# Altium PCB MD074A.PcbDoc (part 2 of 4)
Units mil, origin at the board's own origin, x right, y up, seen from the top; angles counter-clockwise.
Board outline 3224.41 x 4078.74 mil, 4 copper layers (Top Layer, Signal Layer 1, Signal Layer 2, Bottom Layer), stack 61.2 mil thick; 217 components, 121 nets, 624 pads, 901 vias.
Unrouted connection lines stored in the file: 116.
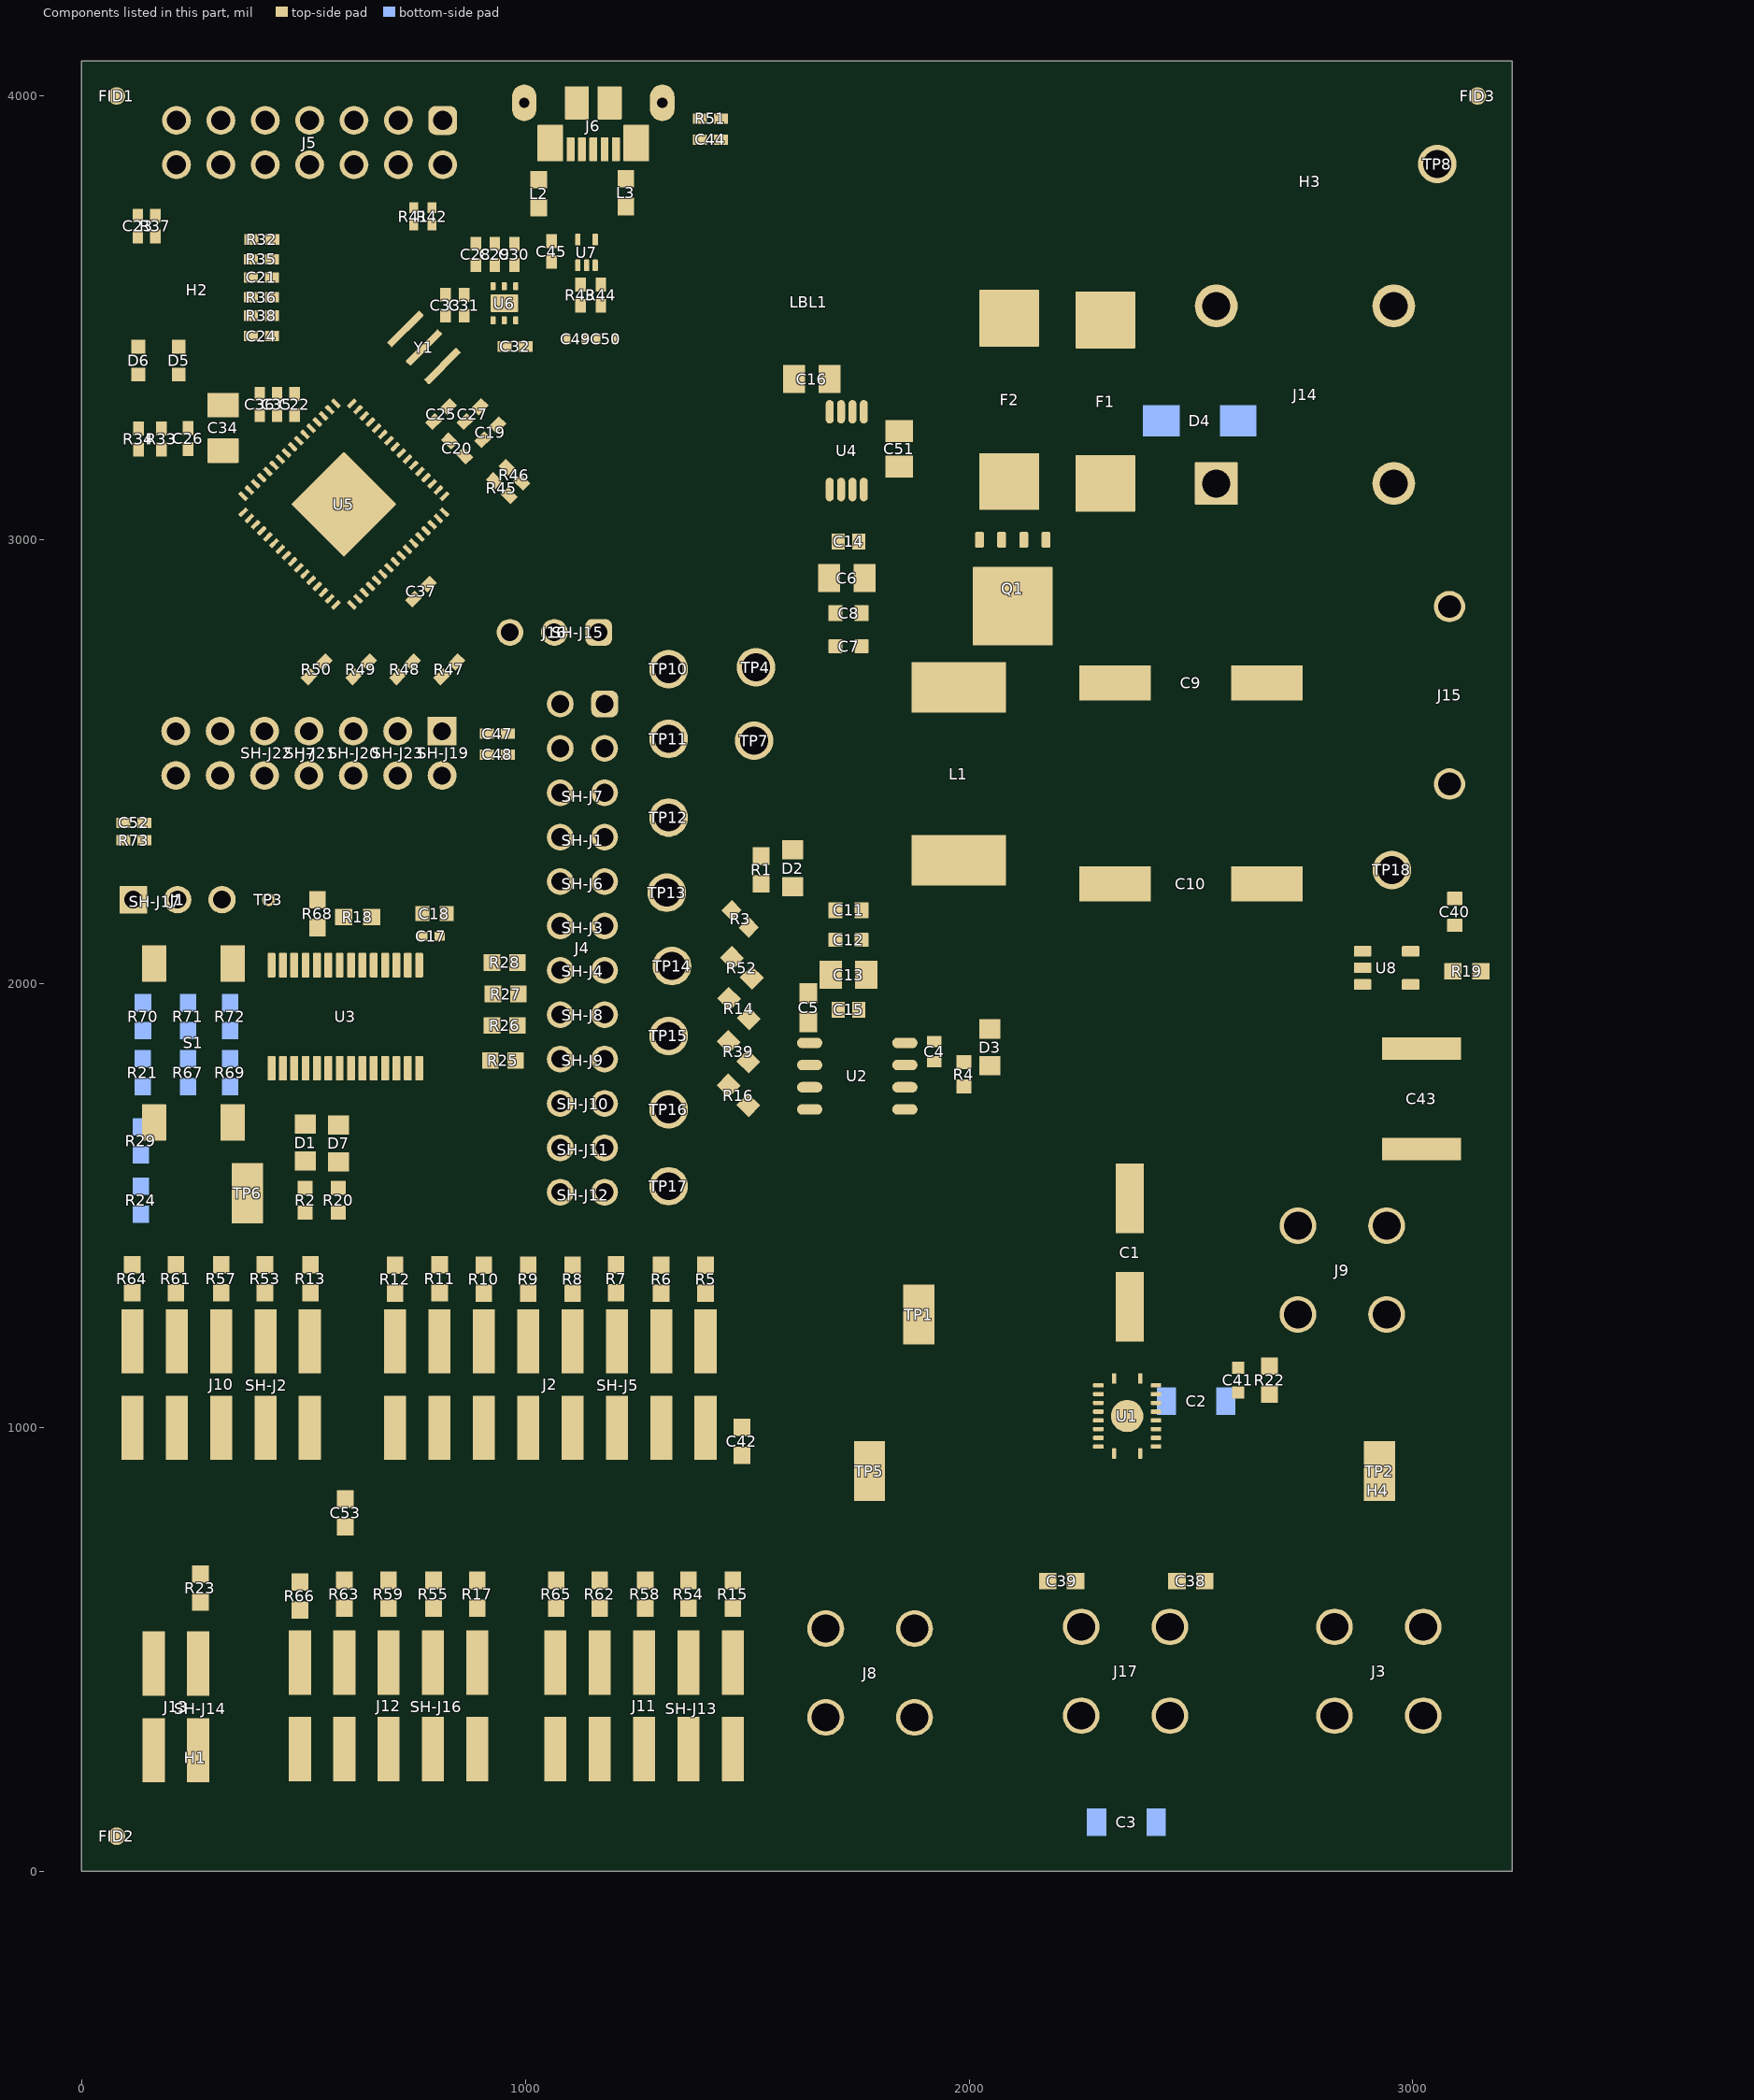
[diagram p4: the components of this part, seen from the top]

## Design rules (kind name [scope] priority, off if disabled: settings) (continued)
PolygonConnect PolygonConnect_17 [All vs IsNamedPolygon('TOP_LAYER_OUT1_P103')] p76: connectstyle=Direct reliefconductorwidth=10 reliefentries=4 polygonreliefangle="90 Angle" airgapwidth=10
PolygonConnect PolygonConnect_16 [All vs IsNamedPolygon('TOP_LAYER_OUT1_P000')] p77: connectstyle=Direct reliefconductorwidth=10 reliefentries=4 polygonreliefangle="90 Angle" airgapwidth=10
PolygonConnect PolygonConnect_15 [All vs IsNamedPolygon('TOP_LAYER_NONET_P093')] p78: connectstyle=Direct reliefconductorwidth=10 reliefentries=4 polygonreliefangle="90 Angle" airgapwidth=10
PolygonConnect PolygonConnect_14 [All vs IsNamedPolygon('TOP_LAYER_OUT2_P099')] p79: connectstyle=Direct reliefconductorwidth=10 reliefentries=4 polygonreliefangle="90 Angle" airgapwidth=10
PolygonConnect PolygonConnect_13 [All vs IsNamedPolygon('TOP_LAYER_OUT1_P000')] p80: connectstyle=Direct reliefconductorwidth=10 reliefentries=4 polygonreliefangle="90 Angle" airgapwidth=10
PolygonConnect PolygonConnect_12 [All vs IsNamedPolygon('BOTTOM_LAYER_NONET_P079') Or  IsNamedPolygon('SIGNAL_LAYER_2_NONET_P078') Or  IsNamedPolygon('SIGNAL_LAYER_1_NONET_P077') Or  IsNamedPolygon('TOP_LAYER_NONET_P083') Or  IsNamedPolygon('BOTTOM_LAYER_NONET_P072') Or  IsNamedPolygon('SIGNAL_LAYER_2_NONET_P070') Or  IsNamedPolygon('SIGNAL_LAYER_1_NONET_P059') Or  IsNamedPolygon('TOP_LAYER_OUT2_P058') Or  IsNamedPolygon('BOTTOM_LAYER_NONET_P056') Or  IsNamedPolygon('SIGNAL_LAYER_2_NONET_P054') Or  IsNamedPolygon('SIGNAL_LAYER_1_NONET_P052') Or  IsNamedPolygon('TOP_LAYER_OUT1_P050') Or  IsNamedPolygon('BOTTOM_LAYER_VM_P044') Or  IsNamedPolygon('SIGNAL_LAYER_2_VM_P042') Or  IsNamedPolygon('SIGNAL_LAYER_1_VM_P040') Or  IsNamedPolygon('TOP_LAYER_VM_P038') Or  IsNamedPolygon('BOTTOM_LAYER_VM_P036') Or  IsNamedPolygon('SIGNAL_LAYER_2_VM_P018') Or  IsNamedPolygon('SIGNAL_LAYER_1_VM_P016') Or  IsNamedPolygon('TOP_LAYER_VM_P002')] p81: connectstyle=Direct reliefconductorwidth=10 reliefentries=4 polygonreliefangle="90 Angle" airgapwidth=10
PolygonConnect PolygonConnect_11 [All vs IsNamedPolygon('TOP_LAYER_NONET_P089') Or  IsNamedPolygon('TOP_LAYER_NONET_P090')] p82: connectstyle=Direct reliefconductorwidth=10 reliefentries=4 polygonreliefangle="90 Angle" airgapwidth=10
PolygonConnect PolygonConnect_10 [All vs IsNamedPolygon('BOTTOM_LAYER_EZFET_USB_SHIELD_P002') Or  IsNamedPolygon('TOP_LAYER_EZFET_USB_SHIELD_P173') Or  IsNamedPolygon('SIGNAL_LAYER_2_EZFET_VBUS_P018') Or  IsNamedPolygon('SIGNAL_LAYER_2_EZFET_VCC_P016')] p83: connectstyle=Direct reliefconductorwidth=10 reliefentries=4 polygonreliefangle="90 Angle" airgapwidth=10
PolygonConnect PolygonConnect_9 [All vs IsNamedPolygon('TOP_LAYER_VM_P123') Or  IsNamedPolygon('TOP_LAYER_VM_P123') Or  IsNamedPolygon('TOP_LAYER_VM_P123')] p84: connectstyle=Direct reliefconductorwidth=10 reliefentries=4 polygonreliefangle="90 Angle" airgapwidth=10
PolygonConnect PolygonConnect_8 [All vs IsNamedPolygon('TOP_LAYER_NONET_P072')] p85: connectstyle=Direct reliefconductorwidth=10 reliefentries=4 polygonreliefangle="90 Angle" airgapwidth=10
PolygonConnect PolygonConnect_7 [All vs IsNamedPolygon('TOP_LAYER_NONET_P072')] p86: connectstyle=Direct reliefconductorwidth=10 reliefentries=4 polygonreliefangle="90 Angle" airgapwidth=10
PolygonConnect PolygonConnect_6 [All vs IsNamedPolygon('TOP_LAYER_VM_P042')] p87: connectstyle=Direct reliefconductorwidth=10 reliefentries=4 polygonreliefangle="90 Angle" airgapwidth=10
PolygonConnect PolygonConnect_5 [All vs IsNamedPolygon('TOP_LAYER_VM_P044')] p88: connectstyle=Direct reliefconductorwidth=10 reliefentries=4 polygonreliefangle="90 Angle" airgapwidth=10
PolygonConnect PolygonConnect_4 [All vs IsNamedPolygon('TOP_LAYER_VM_P046')] p89: connectstyle=Direct reliefconductorwidth=10 reliefentries=4 polygonreliefangle="90 Angle" airgapwidth=10
PolygonConnect PolygonConnect_3 [All vs IsNamedPolygon('TOP_LAYER_GND_P036') Or  IsNamedPolygon('TOP_LAYER_OUT2_P040') Or  IsNamedPolygon('TOP_LAYER_OUT1_P038')] p90: connectstyle=Direct reliefconductorwidth=10 reliefentries=4 polygonreliefangle="90 Angle" airgapwidth=10
PolygonConnect PolygonConnect_2 [InNet('EZFET_VBUS') vs IsNamedPolygon('TOP_LAYER_EZFET_VBUS_P008')] p91: connectstyle=Direct reliefconductorwidth=10 reliefentries=4 polygonreliefangle="90 Angle" airgapwidth=10
PolygonConnect PolygonConnect_1 [InNetClass('Power-Net') vs IsNamedPolygon('TOP_LAYER_EZFET_USB_SHIELD_P173')] p92: connectstyle=Direct reliefconductorwidth=10 reliefentries=4 polygonreliefangle="90 Angle" airgapwidth=10
RoutingVias ThermalPadVias [IsVia and InAnyComponent] p1: holewidth=7.87 width=19.68 viastyle="Through Hole" minholewidth=7.87 minwidth=19.68 maxholewidth=12.99 maxwidth=23.62
RoutingVias [All] p2: holewidth=16 width=34 viastyle="Through Hole" minholewidth=7.87 minwidth=26 maxholewidth=40 maxwidth=65
SilkToBoardRegionClearance [Not ((IsComment or IsDesignator) And (Hide <> 'False')) and not InRegion(1000,500,4000,800)] p1:
SilkToSilkClearance SilkToSilkClearance_Pb-FreeLogo [(HasFootprint('Pb-Free_Overlay_Medium') OR HasFootprint('Pb-Free_Overlay_Small')) vs (HasFootprint('Pb-Free_Overlay_Medium') OR HasFootprint('Pb-Free_Overlay_Small'))] p1: silktosilkclearance=0
SilkToSilkClearance [All] p2: silktosilkclearance=3.94
SilkToSolderMaskClearance SilkToComponentPadClearance [(IsPad or IsFill or IsRegion) and InAnycomponent] p1: minsilkscreentomaskgap=5 clearancetoexposedcopper=TRUE
SilkToSolderMaskClearance "Silk to Solder Mask Opening" [All] p2: minsilkscreentomaskgap=3.94 clearancetoexposedcopper=FALSE
SolderMaskExpansion [All] p1: expansion=1.97 istentingtop=FALSE
UnRoutedNet [All] p1: checkbadconnections=TRUE
Width [All] p1: maxlimit=100 minlimit=6 preferedwidth=10 checkconnectedcopper=TRUE
13 further rules are at their usual default settings.

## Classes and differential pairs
component class MD074A_Hardware: !PCB1 FID1 FID2 FID3 H1 H2 H3 H4 LBL1 Logo1 Logo2 Logo3 Logo4 Logo5 LOGO6 ZZ1 ZZ2 ZZ3 ZZ4
component class MD074A: C1 C2 C3 C4 C5 C6 C7 C8 C9 C10 C11 C12 C13 C14 C15 C16 C17 C18 C38 C39 C40 C41 C42 C43 C51 C52 C53 D1 D2 D3 D4 D7 F1 F2 J1 J2 J3 J4 J8 J9 J10 J11 J12 J13 J14 J15 J16 J17 L1 Q1 R1 R2 R3 R4 R5 R6 R7 R8 R9 R10 R11 R12 R13 R14 R15 R16 R17 R18 R19 R20 R21 R22 R23 R24 R25 R26 R27 R28 R29 R39 R52 R53 R54 R55 R57 R58 R59 R61 R62 R63 R64 R65 R66 R67 R68 R69 R70 R71 R72 R73 S1 SH-J1 SH-J2 SH-J3 SH-J4 SH-J5 SH-J6 SH-J7 SH-J8 SH-J9 SH-J10 SH-J11 SH-J12 SH-J13 SH-J14 SH-J15 SH-J16 SH-J17 TP1 TP2 TP3 TP4 TP5 TP6 TP7 TP8 TP10 TP11 TP12 TP13 TP14 TP15 TP16 TP17 TP18 U1 U2 U3 U4 U8
component class Shunt: SH-J1 SH-J2 SH-J3 SH-J4 SH-J5 SH-J6 SH-J7 SH-J8 SH-J9 SH-J10 SH-J11 SH-J12 SH-J13 SH-J14 SH-J15 SH-J16 SH-J17 SH-J19 SH-J20 SH-J21 SH-J22 SH-J23
net class Power-Net: 3V3_MCU EZFET_VBUS EZFET_VCC GND
component class Header: J2 J5 J7 J10 J11 J12 J13 J16
component class ezFET: C19 C20 C21 C22 C23 C24 C25 C26 C27 C28 C29 C30 C31 C32 C33 C34 C35 C36 C37 C44 C45 C47 C48 C49 C50 D5 D6 J5 J6 J7 L2 L3 R32 R33 R34 R35 R36 R37 R38 R41 R42 R43 R44 R45 R46 R47 R48 R49 R50 R51 SH-J19 SH-J20 SH-J21 SH-J22 SH-J23 U5 U6 U7 Y1
component class Logo: Logo2
component class FiducialMark: FID1 FID2 FID3
component class AssemblyNote: ZZ1 ZZ2 ZZ3 ZZ4
component class Label: LBL1
differential pair USB_D: +USB_D_P -USB_D_N
differential pair EZFET_D: +EZFET_D_P -EZFET_D_N

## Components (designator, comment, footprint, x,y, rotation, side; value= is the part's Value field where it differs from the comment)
C1 "EEE-2AA100UP" SM_RADIAL_E 2362.2,1393.7 r270 top value=10uF
C2 "C3216X7R2A104K160AA" 1206_180 2511.81,1059.06 r180 bottom value=0.1uF
C3 "C3216X7R2A104K160AA" 1206_180 2354.33,110.24 r0 bottom value=0.1uF
C4 "CL10B104JB8NNNC" FP-CL10-0_1-MFG 1921.26,1846.46 r270 top value=0.1uF
C5 "CL10A226MQ8NUNE" FP-CL10-IPC_A 1637.8,1945.94 r90 top value=22uF
C6 "885012207103" 0805_HV 1724.41,2913.39 r0 top value=1uF
C7 "885012206095" FP-885012206095_0603-MFG 1728.35,2759.84 r0 top value=100nF
C8 "CC0603KPX7R9BB103" FP-CC0603-DA-MFG 1728.35,2834.65 r0 top value="10 nF"
C9 "EEE-FK1H151P" SM_RADIAL_G 2500,2677.17 r0 top value=150uF
C10 "EEE-FK1H151P" SM_RADIAL_G 2500,2224.41 r0 top value=150uF
C11 "CC0603KPX7R9BB103" FP-CC0603-DA-MFG 1728.35,2165.35 r0 top value="10 nF"
C12 "885012206095" FP-885012206095_0603-MFG 1728.35,2098.43 r0 top value=100nF
C13 "885012207103" 0805_HV 1728.35,2019.68 r0 top value=1uF
C14 "1nF" FP-C0603C-CF-MFG#1 1732.28,2996.06 r180 top value="1,000 pF"
C15 "1nF" FP-C0603C-CF-MFG#2 1728.35,1940.94 r180 top value="1,000 pF"
C16 "885012007057" 0805_HV 1645.67,3362.2 r180 top value=100pF
C17 "Capacitor" 0402_065L 787.4,2106.3 r0 top value=4.7uF
C18 "885012206020" 0603L 795.28,2157.48 r0 top value=0.1uF
C19 "C1005X5R1A475M050BC" 0402 921.15,3242.01 r45 top value=4.7uF
C20 "GRM155R61A104KA01D" 0402 846.51,3205.86 r315 top value=0.1uF
C21 "C1005C0G1H330J050BA" 0402 405.6,3590.85 r180 top value=33pF
C22 "GRM155R61A104KA01D" 0402 480.31,3305.13 r90 top value=0.1uF
C23 "GRM155R71H102KA01D" 0402 127.1,3706.64 r270 top value=1000pF
C24 "C1005C0G1H330J050BA" 0402 405.6,3458.9 r180 top value=33pF
C25 "GRM155R61A224KE19D" 0402 810.36,3283.06 r45 top value=0.22uF
C26 "GRM155R61C474KE01" 0402 240.16,3228.35 r90 top value=0.47uF
C27 "GRM155R61A224KE19D" 0402 881.2,3283.06 r45 top value=0.22uF
C28 "885012105012" 0402 888.87,3642.71 r90 top value=1uF
C29 "GRM155R61A104KA01D" 0402 931.31,3642.73 r90 top value=0.1uF
C30 "GRM155R71C103KA01D" 0402 975.35,3642.71 r90 top value=0.01uF
C31 "2.2uF" 0402 862.4,3528.56 r90 top
C32 "GRM155R71C103KA01D" 0402 976.95,3435.27 r0 top value=0.01uF
C33 "885012105012" 0402 820.1,3528.56 r90 top value=1uF
C34 "T520A106M010ATE080" 3216-18 318.9,3251.97 r90 top value=10uF
C35 "GRM155R61A104KA01D" 0402 440.55,3305.13 r90 top value=0.1uF
C36 "GRM155R61A104KA01D" 0402 401.77,3305.13 r90 top value=0.1uF
C37 "GRM155R61A104KA01D" 0402 764.94,2883.18 r225 top value=0.1uF
C38 "CGA3E2X7R2A102K080AA" 0603 2500,653.54 r0 top value=1000pF
C39 "CGA3E2X7R2A102K080AA" 0603 2208.66,653.54 r180 top value=1000pF
C40 "GRM188R61E475KE15D" FP-GRM188R61E475KE15D_0603-MFG 3094.49,2161.42 r270 top value=4.7µF
C41 "CGA3E2X7R1E104K080AA" FP-CGA3E-0_3-0_1-MFG 2606.3,1106.3 r90 top
C42 "CGA3E2X7R2A102K080AA" 0603 1488.19,968.5 r90 top value=1000pF
C43 "C5750X7S2A106M230KE" FP-C5750-230-0_5-MFG 3019.68,1740.16 r90 top
C44 "GRM155R61A224KE19D" 0402 1417.32,3901.57 r0 top value=0.22uF
C45 "GRM155R61A104KA01D" 0402 1059.06,3649.61 r90 top value=0.1uF
C47 "GRM1555C1H100FA01D" 0402 937.01,2562.99 r180 top value=10pF
C48 "GRM1555C1H100FA01D" 0402 937.01,2515.75 r180 top value=10pF
C49 "GRM1555C1H100FA01D" 0402S 1113.86,3452.76 r180 top value=10pF
C50 "GRM1555C1H100FA01D" 0402S 1181.42,3452.76 r0 top value=10pF
C51 "C2012X5R1H225K125AB" 0805_HV 1842.52,3204.72 r90 top value=2.2uF
C52 "GRM155R71H102KA01D" 0402 118.11,2362.2 r0 top value=1000pF
C53 "CGA3E2X7R1H104K080AA" 0603 594.49,807.09 r270 top value=0.1uF
D1 "150080VS75000" 0805_A 503.94,1641.73 r90 top
D2 "150080SS75000" 0805_A 1602.36,2259.84 r90 top
D3 "150080VS75000" 0805_A 2047.24,1856.3 r90 top
D4 "SMAJ36CA" FP-SMAJ-CA-MFG 2519.68,3267.72 r180 bottom
D5 "150060RS75000" WL-SMCW_RED 218.95,3403.78 r270 top value=Red
D6 "CMP-0002894-2" WL-SMCW_GREEN 128.28,3403.78 r270 top value=Green
D7 "150080VS75000" 0805_A 578.74,1639.76 r90 top
F1 "0463015.ER" Fuse_0463 2307.09,3311.02 r90 top
F2 "0463030.ER" Fuse_0463 2090.55,3314.96 r90 top
FID1 "Fiducial" Fiducial10-20 78.74,4000 r0 top
FID2 "Fiducial" Fiducial10-20 78.74,78.74 r90 top
FID3 "Fiducial" Fiducial10-20 3145.67,4000 r0 top
H1 "SJ-5303 (CLEAR)" Bumpon_SJ5003Transparent 255.91,255.91 r0 bottom
H2 "SJ-5303 (CLEAR)" Bumpon_SJ5003Transparent 259.84,3562.99 r0 bottom
H3 "SJ-5303 (CLEAR)" Bumpon_SJ5003Transparent 2767.72,3807.09 r0 bottom
H4 "SJ-5303 (CLEAR)" Bumpon_SJ5003Transparent 2921.26,858.27 r180 bottom
J1 "PR20203VBNN" FP-PR20203VBNN-MFG 216.54,2188.98 r0 top
J2 "TSM-108-01-L-DV" Samtec_TSM-108-01-x-DV 1056.38,1096.5 r270 top
J3 "CT3151SP-2" CTE_CT3151SP-2 2923.62,-393.61 r90 top
J4 "67997-224HLF" FCI_67997-224HLF 1128.74,2079.92 r270 top
J5 "61301421121" Wurth_61301421121 514.02,3894.87 r270 top
J6 "CMP-0055311-1" Molex_1051640001 1153.18,4041.52 r180 top
J7 "PEC07DAAN" CONN_PEC07DAAN 512.4,2518.8 r180 top
J8 "CT3151SP-2" CTE_CT3151SP-2 1777.17,-397.54 r90 top
J9 "CT3151SP-2" CTE_CT3151SP-2 3685.04,1354.33 r180 top
J10 "TSM-105-01-L-DV-P" Samtec_TSM-105-01-x-DV 314.57,1096.5 r270 top
J11 "TSM-105-01-L-DV-P" Samtec_TSM-105-01-x-DV 1267.87,372.64 r270 top
J12 "TSM-105-01-L-DV-P" Samtec_TSM-105-01-x-DV 691.99,372.64 r270 top
J13 "TSM-102-01-L-DV" Samtec_TSM-102-01-x-DV 212.6,370.08 r270 top
J14 "691256610002" FP-691256610002_HDR2-MFG 2854.33,3326.77 r90 top
J15 "D3082-05" Harwin_D3082-05 3082.68,2649.61 r90 top
J16 "TSW-103-08-G-S" Samtec_TSW-103-08-x-S 1065.35,2791.34 r180 top
J17 "CT3151SP-0" CTE_CT3151SP-0 2352.76,-393.61 r90 top
L1 "7443320100" WE-HCC_1210 1976.38,2472.44 r270 top value=1uH
L2 "BLM18AG151BH1D" 0603 1030.48,3779.94 r270 top value="150 ohm"
L3 "BLM18AG151BH1D" 0603 1226.54,3782.14 r270 top value="150 ohm"
LBL1 "THT-14-423-10" Label_650x200 1637.8,3535.43 r0 top
Logo1 "CE Mark" CE_Mark_5mm 1322.83,3307.09 r180 bottom
Logo2 "Texas Instruments" TI_Stacked_Overlay_Small 2173.23,3897.64 r0 top
Logo3 "FCC disclaimer" FCC_disclaimer -3134.63,3311.02 r270 bottom
Logo4 "WEEE logo" WEEE_Minimum 1326.75,3023.62 r180 bottom
Logo5 "CAUTION.  READ USER GUIDE BEFORE USE" IEC_Caution_Small 2377.95,1885.83 r0 top
LOGO6 "CAUTION HOT SURFACE" IEC_HotSurface_Small 2039.37,893.7 r0 top
Q1 "CSD18513Q5A" DQJ0008A 2098.43,2889.76 r270 top value=40V
R1 "RC0603JR-0710KL" 0603 1531.5,2255.91 r90 top value=10k
R2 "CMP-0025785-4" 0603L 503.94,1511.81 r90 top value=330
R3 "CMP-0025785-4" 0603L 1484.25,2145.67 r315 top value=330
R4 "CRCW06034K99FKEAC" 0603L 1988.19,1795.28 r270 top value=4.99k
R5 "RC0603FR-07680RL" 0603 1406.38,1333.94 r270 top value=680
R6 "RC0603FR-071KL" 0603 1306.38,1333.94 r270 top value=1.00k
R7 "RC0603FR-071K5L" 0603 1204.72,1334.65 r270 top value=1.50k
R8 "RC0603FR-072K2L" 0603 1106.38,1333.94 r270 top value=2.20k
R9 "RC0603FR-073K3L" 0603 1006.38,1333.94 r270 top value=3.30k
R10 "RC0603FR-074K7L" 0603 906.38,1333.94 r270 top value=4.70k
R11 "RC0603FR-076K8L" 0603 807.09,1334.65 r270 top value=6.80k
R12 "CRCW06038K20JNEA" 0603 706.38,1333.94 r270 top value=8.2k
R13 "PMR03EZPJ000" 0603 515.75,1334.65 r90 top value=0
R14 "PMR03EZPJ000" 0603 1481.67,1943.53 r135 top value=0
R15 "PMR03EZPJ000" 0603 1467.87,623.86 r90 top value=0
R16 "PMR03EZPJ000" 0603 1480.32,1748.03 r135 top value=0
R17 "PMR03EZPJ000" 0603 891.99,623.86 r90 top value=0
R18 "RC0603JR-0747KL" 0603 622.05,2149.61 r180 top value=47k
R19 "PMR03EZPJ000" 0603 3122.05,2027.56 r180 top value=0
R20 "CMP-0025785-4" 0603L 578.74,1511.81 r90 top value=330
R21 "RC0603JR-0710KL" 0603 137.8,1799.21 r90 bottom value=10k
R22 "PMR03EZPJ000" 0603 2677.17,1106.3 r90 top value=0
R23 "PMR03EZPJ000" 0603 267.72,637.8 r90 top value=0
R24 "RC0603JR-0710KL" 0603 133.86,1511.81 r90 bottom value=10k
R25 "CRCW06030000Z0EAHP" RESC1609X55X30NL10T20 949.8,1826.77 r180 top value=0
R26 "CRCW06030000Z0EAHP" RESC1609X55X30NL10T20 953.74,1905.51 r180 top value=0
R27 "CRCW06030000Z0EAHP" RESC1609X55X30NL10T20 955.71,1976.38 r180 top value=0
R28 "CRCW06030000Z0EAHP" RESC1609X55X30NL10T20 953.74,2047.24 r180 top value=0
R29 "RC0603JR-0710KL" 0603 133.86,1645.67 r90 bottom value=10k
R32 "CRCW0402240KFKED" 0402 406.06,3676.49 r180 top value=240k
R33 "CRCW0402470RJNED" 0402 180.25,3226.61 r270 top value=470
R34 "CRCW0402390RJNED" 0402 128.28,3226.61 r270 top value=390
R35 "CRCW0402150KFKED" 0402 405.6,3631.98 r0 top value=150k
R36 "RC0402FR-07220KL" 0402 405.72,3546.49 r180 top value=220k
R37 "CRCW040247K0JNED" 0402 166.47,3706.64 r270 top value=47k
R38 "RC0402FR-07220KL" 0402 405.72,3504.73 r0 top value=220k
R39 "PMR03EZPJ000" 0603 1480.31,1846.46 r135 top value=0
R41 "ERJ-2GE0R00X" 0402L 748.47,3728.65 r90 top value=0
R42 "ERJ-2GE0R00X" 0402L 789.86,3728.65 r90 top value=0
R43 "CRCW040227R0JNED" 0402 1124.38,3551.48 r270 top value=27
R44 "CRCW040227R0JNED" 0402 1170.41,3551.48 r270 top value=27
R45 "CRCW04021K40FKED" 0402 946.89,3116.33 r315 top value=1.40k
R46 "CRCW04021M00JNED" 0402 975.35,3146.36 r135 top value=1.0Meg
R47 "CRCW040210R0FKED" 0402 828.46,2707.95 r225 top value=10.0
R48 "CRCW040210R0FKED" 0402 729.1,2707.95 r225 top value=10.0
R49 "CRCW040210R0FKED" 0402 630.02,2708 r225 top value=10.0
R50 "CRCW040210R0FKED" 0402 529.74,2707.95 r225 top value=10.0
R51 "CRCW040233K0JNED" 0402 1417.32,3948.82 r180 top value=33k
R52 "PMR03EZPJ000" 0603 1488.19,2035.43 r135 top value=0
R53 "CRCW06038K20JNEA" 0603 413.39,1334.65 r270 top value=8.2k
R54 "CRCW06038K20JNEA" 0603 1367.87,623.86 r270 top value=8.2k
R55 "CRCW06038K20JNEA" 0603 793.2,623.86 r270 top value=8.2k
R57 "CRCW060322K0JNEA" 0603 314.96,1334.65 r270 top value=22k
R58 "CRCW060322K0JNEA" 0603 1270.29,623.86 r270 top value=22k
R59 "CRCW060322K0JNEA" 0603 691.99,623.86 r270 top value=22k
R61 "CRCW060347K0FKEA" 0603 212.6,1334.65 r270 top value=47.0k
R62 "CRCW060347K0FKEA" 0603 1167.87,623.86 r270 top value=47.0k
R63 "CRCW060347K0FKEA" 0603 591.99,623.86 r270 top value=47.0k
R64 "CRCW0603100KDHEAP" 0603 114.17,1334.65 r270 top value=100k
R65 "CRCW0603100KDHEAP" 0603 1069.92,623.86 r270 top value=100k
R66 "CRCW0603100KDHEAP" 0603 491.99,620.12 r270 top value=100k
R67 "RC0603JR-0710KL" 0603 240.16,1799.21 r90 bottom value=10k
R68 "RC0603JR-0710KL" 0603 531.5,2157.48 r270 top value=10k
R69 "RC0603JR-0710KL" 0603 334.65,1799.21 r90 bottom value=10k
R70 "RC0603JR-0710KL" 0603 138.63,1925.2 r90 bottom value=10k
R71 "RC0603JR-0710KL" 0603 240.16,1925.2 r90 bottom value=10k
R72 "RC0603JR-0710KL" 0603 334.65,1925.2 r90 bottom value=10k
R73 "CRCW040247K0JNED" 0402 118.11,2322.83 r0 top value=47k
S1 "FSM4JSMA" SW_FSM4JSMA 251.97,1866.14 r0 top
SH-J1 "60900213421" Wurth_60900213421 1129.92,2322.83 r180 top
SH-J2 "60900213421" Wurth_60900213421 417.32,1094.49 r270 top
SH-J3 "60900213421" Wurth_60900213421 1129.92,2125.98 r180 top
SH-J4 "60900213421" Wurth_60900213421 1129.92,2027.56 r180 top
SH-J5 "60900213421" Wurth_60900213421 1208.66,1094.49 r270 top
SH-J6 "60900213421" Wurth_60900213421 1129.92,2224.41 r180 top
SH-J7 "60900213421" Wurth_60900213421 1129.92,2421.26 r180 top
SH-J8 "60900213421" Wurth_60900213421 1129.92,1929.13 r180 top
SH-J9 "60900213421" Wurth_60900213421 1129.92,1826.77 r180 top
SH-J10 "60900213421" Wurth_60900213421 1129.92,1728.35 r180 top
SH-J11 "60900213421" Wurth_60900213421 1129.92,1625.98 r180 top
SH-J12 "60900213421" Wurth_60900213421 1129.92,1523.62 r180 top
SH-J13 "60900213421" Wurth_60900213421 1374.02,366.14 r270 top
SH-J14 "60900213421" Wurth_60900213421 267.72,366.14 r270 top
SH-J15 "60900213421" Wurth_60900213421 1118.11,2791.34 r180 top
SH-J16 "60900213421" Wurth_60900213421 799.21,370.08 r270 top
SH-J17 "60900213421" Wurth_60900213421 165.35,2185.04 r180 top
SH-J19 "60900213421" Wurth_60900213421 814.96,2519.68 r270 top
SH-J20 "60900213421" Wurth_60900213421 614.17,2519.68 r270 top
SH-J21 "60900213421" Wurth_60900213421 515.75,2519.68 r270 top
SH-J22 "60900213421" Wurth_60900213421 417.32,2519.68 r270 top
SH-J23 "60900213421" Wurth_60900213421 712.6,2519.68 r270 top
TP1 "5015" Testpoint_Keystone_Miniature 1887.01,1253.94 r270 top
TP2 "5015" Testpoint_Keystone_Miniature 2925.2,901.57 r270 top
TP3 "TP_H0.45P0.75" TP_H045P075 421.26,2188.98 r90 top
TP4 "5010" Keystone5010 1519.68,2712.6 r0 top
TP5 "5015" Testpoint_Keystone_Miniature 1775.59,901.57 r90 top
TP6 "5015" Testpoint_Keystone_Miniature 374.02,1527.56 r90 top
TP7 "5010" Keystone5010 1515.75,2547.24 r0 top
TP8 "5010" Keystone5010 3055.12,3846.46 r180 top
TP10 "5010" Keystone5010 1322.83,2708.66 r0 top
TP11 "5010" Keystone5010 1322.83,2551.18 r0 top
TP12 "5010" Keystone5010 1322.83,2374.02 r0 top
TP13 "5010" Keystone5010 1318.9,2204.72 r0 top
TP14 "5010" Keystone5010 1330.71,2039.37 r0 top
TP15 "5010" Keystone5010 1322.83,1881.89 r0 top
TP16 "5010" Keystone5010 1322.83,1716.54 r0 top
TP17 "5010" Keystone5010 1322.83,1543.31 r0 top
TP18 "5010" Keystone5010 2952.76,2255.91 r90 top
U1 "DRV8242HQRHLRQ1" RHL0020B-MFG 2356.3,1025.59 r0 top
U2 "LM9036M-3.3/NOPB" D0008A_N 1748.03,1791.34 r0 top
U3 "MSP430G2553IPW28R" PW0028A_N 594.49,1925.2 r270 top
U4 "LM74610QDGKRQ1" DGK0008A_N 1724.41,3200.79 r270 top
U5 "CMP-0039269-4" RGC0064B 591.18,3080.03 r315 top
U6 "TPS73533DRVR" DRV0006A 952.81,3532.82 r90 top
U7 "TPD2E001DRLR" DRL0005A 1137.93,3647.35 r90 top
U8 "TPS7B6950QDBVRQ1" DBV0005A_N 2940.94,2035.43 r0 top
Y1 "CSTNR4M00GH5L000R0" MuRata_CSTNR 771.65,3433.07 r135 top
ZZ1 "This Assembly Note is for PCB labels only" AssemblyNoteLabel 173.67,4752.96 r0 top
ZZ2 "These assemblies are ESD sensitive, ESD precautions shall be observed." AssemblyNote 173.67,4644.07 r0 top
ZZ3 "These assemblies must be clean and free from flux and all contaminants. Use of no clean flux is not acceptable." AssemblyNote 173.67,4555.52 r0 top
ZZ4 "These assemblies must comply with workmanship standards IPC-A-610 Class 2, unless otherwise specified." AssemblyNote 173.67,4466.96 r0 top

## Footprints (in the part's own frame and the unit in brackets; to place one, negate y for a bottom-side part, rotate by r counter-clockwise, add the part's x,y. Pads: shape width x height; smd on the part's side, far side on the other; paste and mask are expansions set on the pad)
0402 [mm] "0402 from SM-752 data"
  rect 0.8x0.6 smd: 1(-0.6,0) 2(0.6,0)
  silkscreen extent -1.22,-0.52 1.22,0.52, body extent -0.55,-0.3 0.55,0.3, height 0.6
0402_065L [mm] "0402"
  rect 0.6x0.5 smd: 1(-0.5,0) 2(0.5,0)
  body extent -0.55,-0.3 0.55,0.3, height 0.65
0402L [mm] "0402 from SM-752 data"
  rect 0.6x0.5 smd: 1(-0.5,0) 2(0.5,0)
  body extent -0.55,-0.3 0.55,0.3, height 0.6
0402S [mil] "Based on C0402S footprint from PADS legacy"
  rect 15x24 smd: 1(-20,0) 2(20,0)
  body extent -22,-12 22,12, height 24
0603 [mm] "0603 from SM-752 data"
  rect 1x0.95 smd: 1(-0.8,0) 2(0.8,0)
  silkscreen extent -1.52,-0.69 1.52,0.69, body extent -0.87,-0.47 0.87,0.47, height 1
0603L [mm] "0603 from SM-752 data"
  rect 0.8x0.85 smd: 1(-0.7,0) 2(0.7,0)
  silkscreen extent -0.07,-0.33 0.07,0.33, body extent -0.87,-0.47 0.87,0.47, height 1
0805_A [mm] "Chip LED, 2-Leads, Body 2.0x1.3mm, IPC Medium Density"
  rect 1.1x1.2 smd: 1(-1.05,0) 2(1.05,0)
  silkscreen extent -0.15,-0.5 0.15,0.5, body extent -1,-0.62 1,0.63, height 0.68
0805_HV [mil] "0805 with 30mil clearance between pads"
  rect 50x63 smd: 1(-40,0) 2(40,0)
  silkscreen extent -74,-40 74,40, body extent -43,-29 43,29, height 57
1206_180 [mm] "1206_180"
  rect 1.1x1.6 smd: 1(-1.7,0) 2(1.7,0)
  silkscreen extent -0.9,-1 0.9,1, body extent -1.75,-0.95 1.75,0.95, height 1.8
3216-18 [mm] "Based on AVX recommendation in http://www.avx.com/download/software/literature/AVX-Footprint-Library.pdf"
  rrect7% 1.4x1.8 smd: 1(-1.3,0) 2(1.3,0)
  silkscreen extent -1.9,-1.13 0.8,1.12, body extent -1.7,-0.9 1.7,0.9, height 1.82
AssemblyNote [mil] "Assembly Note"
AssemblyNoteLabel [mil] "Assembly Note for PCB Labels"
Bumpon_SJ5003Transparent [mil] "3M Hemispherical Bumpon transparent"
  round 1 on Mech4: 0(0,0)
  silkscreen extent -228,-228 228,228, body extent -219,-219 219,219, height 197
CE_Mark_5mm [mil] "Minimum text height for CE Mark"
  silkscreen extent -138,-98 138,98
CONN_PEC07DAAN [mm] "SULLINS"
  rect 1.65x1.65 hole 1.016 mask+0: 1(-7.62,-1.27)
  round 1.65 hole 1.016 mask+0: 2(-7.62,1.27) 3(-5.08,-1.27) 4(-5.08,1.27) 5(-2.54,-1.27) 6(-2.54,1.27) 7(0,-1.27) 8(0,1.27) 9(2.54,-1.27) 10(2.54,1.27) 11(5.08,-1.27) 12(5.08,1.27) 13(7.62,-1.27) 14(7.62,1.27)
  silkscreen extent -9.99,-2.6 8.89,2.54, body extent -8.95,-2.6 8.95,2.6, height 8.38
CTE_CT3151SP-0 [mm] "Banana Jack Insul Nylon Black, R/A, TH"
  round 2.1 hole 1.6: 1(18.898,-2.54) 1(18.898,2.54) 1(23.978,-2.54) 1(23.978,2.54)
  silkscreen extent 0.44,-6.75 18.02,6.75, body extent -3.06,-6.7 24.64,6.8, height 14.37
CTE_CT3151SP-2 [mm] "Banana Jack Insul Nylon Red, R/A, TH"
  round 2.1 hole 1.6: 1(18.898,-2.54) 1(18.898,2.54) 1(23.978,-2.54) 1(23.978,2.54)
  silkscreen extent 0.44,-6.75 18.02,6.75, body extent -3.06,-6.75 24.64,6.75, height 14.37
D0008A_N [mm] "SOIC, 8-Leads, Body 4.9x3.9mm, Pitch 1.27mm, IPC Medium Density"
  oval 1.45x0.6 smd: 1(-2.725,1.905) 2(-2.725,0.635) 3(-2.725,-0.635) 4(-2.725,-1.905) 5(2.725,-1.905) 6(2.725,-0.635) 7(2.725,0.635) 8(2.725,1.905)
  silkscreen extent -3.3,-2.5 0.9,2.5, body extent -3,-2.45 3,2.45, height 1.63
DBV0005A_N [mm] "SOT23, 5-Leads, Body 2.9x1.6mm, Pitch 0.95mm, Lead Span 2.8mm, IPC Medium Density"
  rrect17% 1x0.6 smd: 1(-1.375,0.95) 2(-1.375,0) 3(-1.375,-0.95) 4(1.375,-0.95) 5(1.375,0.95)
  silkscreen extent -1.63,-1.55 0.38,1.55, body extent -1.42,-1.46 1.42,1.46, height 1.09
DGK0008A_N [mm] "TSOP, 8-Leads, Body 3x3mm, Pitch 0.65mm, IPC Medium Density"
  oval 1.35x0.45 smd: 1(-2.225,0.975) 2(-2.225,0.325) 3(-2.225,-0.325) 4(-2.225,-0.975) 5(2.225,-0.975) 6(2.225,-0.325) 7(2.225,0.325) 8(2.225,0.975)
  silkscreen extent -2.75,-1.55 0.95,1.55, body extent -2.45,-1.5 2.45,1.5, height 0.96
DQJ0008A [mm] "SMD, 8-Leads, Body 5.75x4.9mm"
  rrect39% 0.91x0.51 smd paste-0.05 mask-0.05: 1(-2.795,1.905) 2(-2.795,0.635) 3(-2.795,-0.635) 4(-2.795,-1.905) 5(2.795,-1.905) 6(2.795,-0.635) 7(2.795,0.635) 8(2.795,1.905)
  rrect8% 1.58x1.25 on Top Paste: 9(-0.38,1.45) 9(-0.38,0) 9(-0.38,-1.45) 9(1.4,1.45) 9(1.4,0) 9(1.4,-1.45)
  rrect3% 3.48x4.47 on Top Solder: 9(0.55,0)
  rrect2% 4.49x4.57 smd paste-2.5 mask-2.5: 9(1.005,0)
  silkscreen extent -3,-2.6 3,2.6, body extent -3.13,-2.45 3.13,2.45, height 1.15
DRL0005A [mm] "SOTFL, 5-Flat Leads, Body 1.2x1.6x0.6mm, Pitch 0.5mm, TI recommended"
  rrect33% 0.67x0.3 smd: 1(-0.74,0.5) 2(-0.74,0) 3(-0.74,-0.5) 4(0.74,-0.5) 5(0.74,0.5)
  silkscreen extent -0.9,-0.95 0.5,0.95, body extent -0.85,-0.85 0.85,0.85, height 0.62
DRV0006A [mm] "SON, 6-Leads, Body 2x2mm, Pitch 0.65mm, Thermal Pad 1.6x1mm, TI Recommended"
  rrect33% 0.45x0.3 smd: 1(-0.975,0.65) 2(-0.975,0) 3(-0.975,-0.65) 4(0.975,-0.65) 5(0.975,0) 6(0.975,0.65)
  rrect14% 1x0.7 on Top Paste: 7(0,0.45) 7(0,-0.45)
  rrect10% 1x1.6 smd paste-0.5: 7(0,0)
  silkscreen extent -1.05,-1.2 1.05,1.2, body extent -1.05,-1.05 1.05,1.05, height 0.81
FCC_disclaimer [mil]
FCI_67997-224HLF [mm] "Header, 2.54mm, 12x2, TH"
  rrect50% 1.53x1.53 hole 1.02: 1(-13.97,1.27)
  round 1.53 hole 1.02: 2(-13.97,-1.27) 3(-11.43,1.27) 4(-11.43,-1.27) 5(-8.89,1.27) 6(-8.89,-1.27) 7(-6.35,1.27) 8(-6.35,-1.27) 9(-3.81,1.27) 10(-3.81,-1.27) 11(-1.27,1.27) 12(-1.27,-1.27) 13(1.27,1.27) 14(1.27,-1.27) 15(3.81,1.27) 16(3.81,-1.27) 17(6.35,1.27) 18(6.35,-1.27) 19(8.89,1.27) 20(8.89,-1.27) 21(11.43,1.27) 22(11.43,-1.27) 23(13.97,1.27) 24(13.97,-1.27)
  body extent -15.24,-2.42 15.24,2.42, height 8.71
Fiducial10-20 [mm]
  round 1 smd mask+0.5: 1(0,0)
  Top Layer keep-out circle w1.178: c0,0 r0.5
FP-691256610002_HDR2-MFG [mm]
  rrect4% 2.45x2.45 hole 1.6 paste-2539.97 mask+0: 1(-5.08,7.55)
  round 2.45 hole 1.6 paste-2539.97 mask+0: 1(-5.08,-2.61) 2(5.08,7.55) 2(5.08,-2.61)
  silkscreen extent -11,-9.2 10.21,9.2, body extent -10.31,-9.3 10.31,9.3, height 0.25
FP-885012206095_0603-MFG [mm]
  rrect13% 0.8x0.8 smd paste+0 mask+0: 1(-0.75,0) 2(0.75,0)
  silkscreen extent -0.85,-0.77 0.85,0.77, body extent -1.25,-0.55 1.25,0.55, height 0.25
FP-C0603C-CF-MFG#1 [mm]
  rect 0.75x0.9 smd paste+0 mask+0: 1(-0.5,0) 2(0.7,0)
  silkscreen extent -0.78,-0.85 0.98,0.85, body extent -1.1,-0.6 1.3,0.6, height 0.25
FP-C0603C-CF-MFG#2 [mm]
  rect 0.75x0.9 smd paste+0 mask+0: 1(-0.6,0) 2(0.6,0)
  silkscreen extent -0.87,-0.85 0.88,0.85, body extent -1.2,-0.6 1.2,0.6, height 0.25
FP-C5750-230-0_5-MFG [mm]
  rect 1.3x4.5 smd paste+0 mask+0: 1(-2.875,0) 2(2.875,0)
  silkscreen extent -3.1,-2.7 3.1,2.7, body extent -3.62,-2.8 3.62,2.8, height 0.25
FP-CC0603-DA-MFG [mm]
  rect 0.8x0.9 smd paste+0 mask+0: 1(-0.75,0) 2(0.75,0)
  silkscreen extent -0.85,-0.85 0.85,0.85, body extent -1.35,-0.75 1.35,0.75, height 0.25
FP-CGA3E-0_3-0_1-MFG [mm]
  rect 0.7x0.7 smd paste+0 mask+0: 1(-0.7,0) 2(0.7,0)
  silkscreen extent -0.95,-0.72 0.95,0.72, body extent -0.8,-0.4 0.8,0.4, height 1.1
FP-CL10-0_1-MFG [mm]
  rect 0.625x0.825 smd paste+0 mask+0: 1(-0.575,0) 2(0.575,0)
  silkscreen extent -0.8,-0.79 0.8,0.79, body extent -0.99,-0.55 0.99,0.55, height 0.25
FP-CL10-IPC_A [mil]
  rect 45.6x39.85 smd paste+0 mask+0: 1(-32.56,0) 2(32.56,0)
  silkscreen extent -55,-36 55,36, body extent -75,-40 75,40, height 10
FP-GRM188R61E475KE15D_0603-MFG [mm]
  rrect13% 0.75x0.9 smd paste+0 mask+0: 1(-0.775,0) 2(0.775,0)
  silkscreen extent -0.9,-0.9 0.9,0.9, body extent -1.25,-0.6 1.25,0.6, height 0.25
FP-PR20203VBNN-MFG [mm]
  rect 1.57x1.57 hole 1.02 paste-2539.97 mask+0: 1(-2.54,0)
  round 1.57 hole 1.02 paste-2539.97 mask+0: 2(0,0) 3(2.54,0)
  silkscreen extent -4.7,-1.25 3.81,1.25, body extent -3.91,-1.35 3.91,1.35, height 0.25
FP-SMAJ-CA-MFG [mm]
  rect 2.1x1.8 smd paste+0 mask+0: 1(-2.2,0) 2(2.2,0)
  silkscreen extent -2.3,-1.4 2.3,1.39, body extent -2.55,-1.34 2.55,1.33, height 2.29
Fuse_0463 [mm] "SMD, 2-Leads, Body 10.1x3.12mm"
  rrect3% 3.25x3.43 smd: 1(-4.675,0) 2(4.675,0)
  silkscreen extent -2.6,-1.5 2.6,1.5, body extent -5.05,-1.56 5.05,1.56, height 3.12
Harwin_D3082-05 [mm] "Shorting Plug, 10.16mm spacing, TH"
  round 1.8 hole 1.3: 1(-5.08,0) 2(5.08,0)
  silkscreen extent -3.9,-0.53 3.9,0.53, body extent -5.6,-0.52 5.61,0.52, height 6.63
IEC_Caution_Small [mil]
  silkscreen extent -107,-93 107,92
IEC_HotSurface_Small [mil]
  silkscreen extent -107,-93 107,92
Keystone5010 [mil] "Keystone Multipurpose loops"
  round 87 hole 63: 1(0,0)
  silkscreen extent -70,-70 70,70, body extent -63,-63 63,62, height 319
Label_650x200 [mil] "Thermal Transfer Label"
  round 1 on Mech13: 0(0,0)
  silkscreen extent -325,-100 325,100, body extent -325,-100 325,100, height 1
Molex_1051640001 [mm] "Receptacle, USB 2.0, Micro B, 5 Pos, 0.65mm Pitch, R/A, SMT"
  rrect22% 0.45x1.38 smd: 1(1.3,4.11) 2(0.65,4.11) 3(0,4.11) 4(-0.65,4.11) 5(-1.3,4.11)
  rrect7% 1.475x2.1 smd: 6(-2.462,3.75) 11(2.462,3.75)
  rrect100% 1.4x2.1 hole 0.6 slot 1.3 at 90 deg: 7(-3.95,1.45) 10(3.95,1.45)
  rrect7% 1.375x1.9 smd: 8(-0.938,1.45) 9(0.938,1.45)
  silkscreen extent 1.2,5.1 1.4,5.4, body extent -4.1,-0.7 4.1,4.47, height 2.45
MuRata_CSTNR [mm] "SMD, 3-Leads, Body 4.5x2mm, Pitch 1.5mm"
  rrect25% 0.4x2.6 smd: 1(-1.5,0) 2(0,0) 3(1.5,0)
  body extent -2.3,-1.05 2.3,1.05, height 1.2
PW0028A_N [mm] "SOP, 28-Leads, Body 9.8x4.5mm, Pitch 0.65mm, IPC Medium Density"
  rrect22% 1.4x0.45 smd: 1(-2.95,4.225) 2(-2.95,3.575) 3(-2.95,2.925) 4(-2.95,2.275) 5(-2.95,1.625) 6(-2.95,0.975) 7(-2.95,0.325) 8(-2.95,-0.325) 9(-2.95,-0.975) 10(-2.95,-1.625) 11(-2.95,-2.275) 12(-2.95,-2.925) 13(-2.95,-3.575) 14(-2.95,-4.225) 15(2.95,-4.225) 16(2.95,-3.575) 17(2.95,-2.925) 18(2.95,-2.275) 19(2.95,-1.625) 20(2.95,-0.975) 21(2.95,-0.325) 22(2.95,0.325) 23(2.95,0.975) 24(2.95,1.625) 25(2.95,2.275) 26(2.95,2.925) 27(2.95,3.575) 28(2.95,4.225)
  silkscreen extent -3.07,-4.9 1.85,5.13, body extent -3.21,-4.85 3.21,4.85, height 1
RESC1609X55X30NL10T20 [mm] "Chip Resistor, 2-Leads, Body 1.60x0.85mm, IPC Medium Density"
  rect 0.95x0.95 smd: 1(-0.725,0) 2(0.725,0)
  body extent -0.85,-0.48 0.85,0.48, height 0.55
RGC0064B [mm] "VQFN-64"
  rrect42% 0.6x0.24 smd mask+0.07: 1(-4.4,3.75) 2(-4.4,3.25) 3(-4.4,2.75) 4(-4.4,2.25) 5(-4.4,1.75) 6(-4.4,1.25) 7(-4.4,0.75) 8(-4.4,0.25) 9(-4.4,-0.25) 10(-4.4,-0.75) 11(-4.4,-1.25) 12(-4.4,-1.75) 13(-4.4,-2.25) 14(-4.4,-2.75) 15(-4.4,-3.25) 16(-4.4,-3.75) 33(4.4,-3.75) 34(4.4,-3.25) 35(4.4,-2.75) 36(4.4,-2.25) 37(4.4,-1.75) 38(4.4,-1.25) 39(4.4,-0.75) 40(4.4,-0.25) 41(4.4,0.25) 42(4.4,0.75) 43(4.4,1.25) 44(4.4,1.75) 45(4.4,2.25) 46(4.4,2.75) 47(4.4,3.25) 48(4.4,3.75)
  rrect42% 0.24x0.6 smd mask+0.07: 17(-3.75,-4.4) 18(-3.25,-4.4) 19(-2.75,-4.4) 20(-2.25,-4.4) 21(-1.75,-4.4) 22(-1.25,-4.4) 23(-0.75,-4.4) 24(-0.25,-4.4) 25(0.25,-4.4) 26(0.75,-4.4) 27(1.25,-4.4) 28(1.75,-4.4) 29(2.25,-4.4) 30(2.75,-4.4) 31(3.25,-4.4) 32(3.75,-4.4) 49(3.75,4.4) 50(3.25,4.4) 51(2.75,4.4) 52(2.25,4.4) 53(1.75,4.4) 54(1.25,4.4) 55(0.75,4.4) 56(0.25,4.4) 57(-0.25,4.4) 58(-0.75,4.4) 59(-1.25,4.4) 60(-1.75,4.4) 61(-2.25,4.4) 62(-2.75,4.4) 63(-3.25,4.4) 64(-3.75,4.4)
  rrect2% 4.25x4.25 smd paste-2.112: 65(0,0)
  body extent -4.5,-4.5 4.5,4.5, height 1
RHL0020B-MFG [mm]
  rrect40% 0.25x0.6 smd paste+0 mask+0: 1(-0.75,2.15) 10(-0.75,-2.15) 11(0.75,-2.15) 20(0.75,2.15)
  rrect40% 0.6x0.25 smd paste+0 mask+0: 2(-1.65,1.75) 3(-1.65,1.25) 4(-1.65,0.75) 5(-1.65,0.25) 6(-1.65,-0.25) 7(-1.65,-0.75) 8(-1.65,-1.25) 9(-1.65,-1.75) 12(1.65,-1.75) 13(1.65,-1.25) 14(1.65,-0.75) 15(1.65,-0.25) 16(1.65,0.25) 17(1.65,0.75) 18(1.65,1.25) 19(1.65,1.75)
  round 1.845 smd paste-1000 mask+0: 21(0,0)
  Top Layer region: -1.025,1.475 -1.018,1.5 -1,1.518 -0.975,1.525 -0.975,1.525 -0.375,1.525 -0.375,2.4 -0.368,2.425 -0.35,2.443 -0.325,2.45 -0.325,2.45 -0.175,2.45 -0.156,2.446 -0.14,2.435 -0.129,2.419 -0.125,2.4 -0.125,2.4 -0.125,1.925 0.125,1.925 0.125,2.4 0.129,2.419 0.14,2.435 0.156,2.446 0.175,2.45 0.175,2.45 0.325,2.45 0.35,2.443 0.368,2.425 0.375,2.4 0.375,2.4 0.375,1.525 0.975,1.525 1,1.518 1.018,1.5 1.025,1.475 1.025,1.475 1.025,-1.475 1.018,-1.5 1,-1.518 0.975,-1.525 0.975,-1.525 0.375,-1.525 0.375,-2.4 0.368,-2.425 0.35,-2.443 0.325,-2.45 0.325,-2.45 0.175,-2.45 0.156,-2.446 0.14,-2.435 0.129,-2.419 0.125,-2.4 0.125,-2.4 0.125,-1.925 -0.125,-1.925 -0.125,-2.4 -0.129,-2.419 -0.14,-2.435 -0.156,-2.446 -0.175,-2.45 -0.175,-2.45 -0.325,-2.45 -0.35,-2.443 -0.368,-2.425 -0.375,-2.4 -0.375,-2.4 -0.375,-1.525 -0.975,-1.525 -1,-1.518 -1.018,-1.5 -1.025,-1.475 -1.025,-1.475
  silkscreen extent -1.8,-2.3 1.8,3.12, body extent -1.75,-2.25 1.75,2.25, height 1
Samtec_TSM-102-01-x-DV [mm] "Header, 2.54mm, 2x2, SMT"
  rect 3.68x1.27 smd: 1(-2.475,1.27) 2(2.475,1.27) 3(-2.475,-1.27) 4(2.475,-1.27)
  silkscreen extent -1.75,-2.54 1.65,2.63, body extent -3.85,-2.54 3.85,2.54, height 9.65
Samtec_TSM-105-01-x-DV [mm] "Header, 2.54mm, 5x2, SMT"
  rect 3.68x1.27 smd: 1(-2.475,5.08) 2(2.475,5.08) 3(-2.475,2.54) 4(2.475,2.54) 5(-2.475,0) 6(2.475,0) 7(-2.475,-2.54) 8(2.475,-2.54) 9(-2.475,-5.08) 10(2.475,-5.08)
  silkscreen extent -1.65,-6.35 1.65,6.49, body extent -3.85,-6.35 3.85,6.35, height 9.65
Samtec_TSM-108-01-x-DV [mm] "Header, 2.54mm, 8x2, SMT"
  rect 3.68x1.27 smd: 1(-2.475,8.89) 2(2.475,8.89) 3(-2.475,6.35) 4(2.475,6.35) 5(-2.475,3.81) 6(2.475,3.81) 7(-2.475,1.27) 8(2.475,1.27) 9(-2.475,-1.27) 10(2.475,-1.27) 11(-2.475,-3.81) 12(2.475,-3.81) 13(-2.475,-6.35) 14(2.475,-6.35) 15(-2.475,-8.89) 16(2.475,-8.89)
  silkscreen extent -1.65,-10.16 1.65,10.3, body extent -3.85,-10.16 3.85,10.16, height 9.65
Samtec_TSW-103-08-x-S [mm] "Header, 2.54mm, 3x1, TH"
  rrect50% 1.53x1.53 hole 1.02: 1(-2.54,0)
  round 1.53 hole 1.02: 2(0,0) 3(2.54,0)
  body extent -3.94,-1.27 3.81,1.27, height 8.38
SM_RADIAL_E [mm] "8 x 6.2mm:  Panasonic E"
  rect 4x1.6 smd: 1(-3.1,0) 2(3.1,0)
  silkscreen extent -4.25,-4.25 4.25,4.25, body extent -4.25,-4.25 4.25,4.25, height 6.5
SM_RADIAL_G [mm] "10 x 10.2mm:  Panasonic G"
  rect 4.1x2 smd: 1(-4.35,0) 2(4.35,0)
  silkscreen extent -5.35,-5.35 5.35,5.35, body extent -5.25,-5.25 5.25,5.25, height 10.5
SW_FSM4JSMA [mm] "Alcoswitch"
  rrect7% 1.4x2.1 smd: 1(2.25,4.55) 2(2.25,-4.55) 3(-2.25,4.55) 4(-2.25,-4.55)
  body extent -3,-5 3,5, height 5.09
Testpoint_Keystone_Miniature [mil] "Miniature SMT test point"
  rect 135x70 smd: 1(0,0)
  silkscreen extent -78,-46 78,45, body extent -52,-20 52,20, height 61
TI_Stacked_Overlay_Small [mil]
  silkscreen extent -418,-98 418,98
TP_H045P075 [mm] "TP_H0.45P0.75"
  round 0.75 hole 0.45: 1(0,0)
WE-HCC_1210 [mm] "WURTH"
  rect 2.9x5.4 smd: 1(-4.95,0) 2(4.95,0)
  silkscreen extent -6,-5.9 6,5.9, body extent -6,-5.85 6,5.85, height 10
WEEE_Minimum [mil] "WEEElie bin"
  silkscreen extent -95,-172 99,104
WL-SMCW_GREEN [mm] "WURTH"
  rect 0.8x0.8 smd: 1(-0.8,0) 2(0.8,0)
  silkscreen extent -1.9,-0.8 1.2,0.8, body extent -0.85,-0.45 0.85,0.45, height 0.8
WL-SMCW_RED [mm] "WURTH"
  rect 0.8x0.8 smd: 1(-0.8,0) 2(0.8,0)
  silkscreen extent -1.9,-0.8 1.2,0.8, body extent -0.85,-0.45 0.85,0.45, height 0.8
Wurth_60900213421 [mil] "Shunt, 2.54mm, Black"
  round 1 on Mech3: 0(0,0)
  body extent -98,-48 98,48, height 338
Wurth_61301421121 [mm] "Header, 2.54mm, 7x2, TH"
  rrect50% 1.65x1.65 hole 1.1: 1(-1.27,7.62)
  round 1.65 hole 1.1: 2(1.27,7.62) 3(-1.27,5.08) 4(1.27,5.08) 5(-1.27,2.54) 6(1.27,2.54) 7(-1.27,0) 8(1.27,0) 9(-1.27,-2.54) 10(1.27,-2.54) 11(-1.27,-5.08) 12(1.27,-5.08) 13(-1.27,-7.62) 14(1.27,-7.62)
  body extent -2.54,-8.89 2.54,8.89, height 8.55

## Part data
C1: library part CMP-0011164-2, "CAP, AL, 10 uF, 100 V, +/- 20%, AEC-Q200 Grade 3, SMD", Alternate Manufacturer="Wurth Elektronik", Alternate PartNumber=865080845005, Cap_Case=8.0x6.0mm, Manufacturer=Panasonic, Supplier Part Number 1=PCE3966CT-ND, Tolerance_%=20%, Value1=Unknown, Value2=100V, ValueDisplayed=10uF
C2 C3: library part CMP-0008709-2, "CAP, CERM, 0.1 uF, 100 V, +/- 10%, X7R, 1206", Cap_Case=1206_180, Manufacturer=TDK, Supplier Part Number 1=445-1377-1-ND, TempCo=X7R, Tolerance_%=10%, Value1="0.030343 ohm", Value2=100V, ValueDisplayed=0.1uF
C4: library part CMP-13271-000011-1, "CAP CER 0.1UF 50V X7R 0603", Alternative Manufacturer="Wurth Elektronik", Alternative PartNumber=885012206095, Capacitance=100nF, Manufacturer="Samsung Electro-Mechanics America, Inc", Package=CL10-0.1, Temperature="-55°C to +125°C", Temperature Characteristic=X7R, Temperature Coefficient=15%, Temperature Range High=+125°C, Temperature Range Low=-55°C, Tolerance=5%, Voltage Rating=50V
C5: library part CMP-13271-003053-1, "Cap Ceramic 22uF 6.3V X5R ±20% Pad SMD 0603 +85°C T/R", Case Code (Imperial)=0603, Case Code (Metric)=1608, Manufacturer=Samsung, Max Operating Temperature=85°C, Min Operating Temperature=-55°C, Tolerance=20%, Voltage Rating=6.3V
C6 C13: library part CMP-0007696-2, "CAP, CERM, 1 uF, 50 V, +/- 10%, X7R, 0805", Cap_Case=0805, Manufacturer="Wurth Elektronik", Supplier Part Number 1=710-885012207103, TempCo=X7R, Tolerance_%=10%, Value1=Unknown, Value2=50V, ValueDisplayed=1uF
C7 C12: library part CMP-0097346-1, "0.1 µF ±10% 50V Ceramic Capacitor X7R 0603 (1608 Metric)", Digikey Part Number=732-8013-1-ND, Manufacturer=Wurth, Mouser Part Number=710-885012206095, Operating Temperature Range="-55°C to +125°C", TempCo=15%, Temperature Characteristic=X7R, Tolerance_%=10%, ValueDisplayed=100nF
C8 C11: library part CMP-1035-02321-3, "CAP CER 10000PF 50V X7R 0603", Alternate Manufacturer="Wurth Elektronik", Alternate PartNumber=885012206089, Capacitance="10 nF", Manufacturer=YAGEO, Temperature="-55°C to +125°C", Temperature Characteristic=X7R, Temperature Coefficient=15%, Temperature Range High=+125°C, Temperature Range Low=-55°C, Tolerance=0.1, Voltage="50 V"
C9 C10: library part CMP-0011178-2, "CAP, AL, 150 uF, 50 V, +/- 20%, 0.18 ohm, AEC-Q200 Grade 2, SMD", Alternate Manufacturer="Wurth Elektronik", Alternate PartNumber=865080657017, Cap_Case=G, Manufacturer=Panasonic, Supplier Part Number 1=PCE3810CT-ND, Tolerance_%=20%, Value1="0.18 ohm", Value2=50V, ValueDisplayed=150uF
C14 C15: library part CMP-03020-030804-1, "CAP CER 1000PF 50V X7R 0603", Alternate Manufacturer="Wurth Elektronik", Alternate PartNumber=885012206083, Capacitance="1,000 pF", Manufacturer=KEMET, Package=C0603C-CF, PartNumber=C0603C102J5RACAUTO, Temperature="-55°C to +125°C", Temperature Characteristic=X7R, Temperature Coefficient=30ppm/°C, Temperature Range High=+125°C, Temperature Range Low=-55°C, Tolerance=0.05, Voltage Rating="50 V"
C16: library part CMP-0081453-1, "CAP, CERM, 100 pF, 50 V,+/- 5%, C0G/NP0, 0805", Cap_Case=0805, Manufacturer="Wurth Elektronik", Supplier Part Number 1=732-7852-1-ND, TempCo=C0G/NP0, Tolerance_%=5%, Value2=50V, ValueDisplayed=100pF
C17: library part CMP-0006268-2, "CAP, CERM, 4.7 uF, 10 V, +/- 10%, X5R, 0402", Alternate Manufacturer="Wurth Elektronik", Alternate PartNumber=885012106012, Cap_Case=0402_065, Manufacturer=TDK, PartNumber=C1005X5R1A475K050BC, Supplier Part Number 1=445-13820-1-ND, TempCo=X5R, Tolerance_%=10%, Value1="0.003417 ohm", Value2=10V, ValueDisplayed=4.7uF
C18: library part CMP-0064931-4, "CAP, CERM, 0.1 uF, 10 V,+/- 10%, X7R, 0603", Cap_Case=0603, Manufacturer="Wurth Elektronik", Supplier Part Number 1=732-7939-1-ND, TempCo=X7R, Tolerance_%=10%, Value1=Unknown, Value2=10V, ValueDisplayed=0.1uF
C19: library part CMP-0006269-2, "CAP, CERM, 4.7 uF, 10 V, +/- 20%, X5R, 0402", Alternate Manufacturer="Wurth Elektronik", Alternate PartNumber=885012106012, Cap_Case=0402, Manufacturer=TDK, Supplier Part Number 1=445-8023-1-ND, TempCo=X5R, Tolerance_%=20%, Value1=Unknown, Value2=10V, ValueDisplayed=4.7uF
C20 C22 C29 C35 C36 C37 C45: library part CMP-0006562-2, "CAP, CERM, 0.1 uF, 10 V, +/- 10%, X5R, 0402", Alternate Manufacturer="Wurth Elektronik", Alternate PartNumber=885012105010, Cap_Case=0402, Manufacturer=MuRata, Supplier Part Number 1=490-1318-1-ND, TempCo=X5R, Tolerance_%=10%, Value1=Unknown, Value2=10V, ValueDisplayed=0.1uF
C21 C24: library part CMP-0006250-2, "CAP, CERM, 33 pF, 50 V, +/- 5%, C0G/NP0, 0402", Alternate Manufacturer="Wurth Elektronik", Alternate PartNumber=885012005058, Cap_Case=0402, Manufacturer=TDK, Supplier Part Number 1=445-1241-1-ND, TempCo=C0G/NP0, Tolerance_%=5%, Value1=Unknown, Value2=50V, ValueDisplayed=33pF
C23 C52: library part CMP-0006673-2, "CAP, CERM, 1000 pF, 50 V, +/- 10%, X7R, 0402", Alternate Manufacturer="Wurth Elektronik", Alternate PartNumber=885012205061, Cap_Case=0402, Manufacturer=MuRata, Supplier Part Number 1=490-1303-1-ND, TempCo=X7R, Tolerance_%=10%, Value1=Unknown, Value2=50V, ValueDisplayed=1000pF
C25 C27 C44: library part CMP-0006570-2, "CAP, CERM, 0.22 uF, 10 V, +/- 10%, X5R, 0402", Alternate Manufacturer="Wurth Elektronik", Alternate PartNumber=885012105011, Cap_Case=0402, Manufacturer=MuRata, Supplier Part Number 1=490-3910-1-ND, TempCo=X5R, Tolerance_%=10%, Value1=Unknown, Value2=10V, ValueDisplayed=0.22uF
C26: library part CMP-0006600-2, "CAP, CERM, 0.47 uF, 16 V, +/- 10%, X5R, 0402", Cap_Case=0402, Manufacturer=MuRata, TempCo=X5R, Tolerance_%=10%, Value1=Unknown, Value2=16V, ValueDisplayed=0.47uF
C28 C33: library part CMP-0064924-2, "CAP, CERM, 1 uF, 10 V,+/- 20%, X5R, 0402", Cap_Case=0402, Manufacturer="Wurth Elektronik", Supplier Part Number 1=732-7489-1-ND, TempCo=X5R, Tolerance_%=20%, Value1=Unknown, Value2=10V, ValueDisplayed=1uF
C30: library part CMP-0006639-2, "CAP, CERM, 0.01 uF, 16 V, +/- 10%, X7R, 0402", Alternate Manufacturer="Wurth Elektronik", Alternate PartNumber=885012205031, Cap_Case=0402, Manufacturer=MuRata, Supplier Part Number 1=490-1313-1-ND, TempCo=X7R, Tolerance_%=10%, Value1=Unknown, Value2=16V, ValueDisplayed=0.01uF
C31: library part CMP-0006594-2, "CAP, CERM, 2.2 uF, 16 V, +/- 10%, X5R, 0402", Cap_Case=0402, Manufacturer=MuRata, PartNumber=GRM155R61C225KE11D, Supplier Part Number 1=490-10695-1-ND, TempCo=X5R, Tolerance_%=10%, Value1=Unknown, Value2=16V
C32: library part CMP-0006639-2, "CAP, CERM, 0.01 uF, 16 V, +/- 10%, X7R, 0402", Cap_Case=0402, Manufacturer=MuRata, Supplier Part Number 1=490-1313-1-ND, TempCo=X7R, Tolerance_%=10%, Value1=Unknown, Value2=16V, ValueDisplayed=0.01uF
C34: library part CMP-0084376-1, "CAP, Tantalum Polymer, 10 µF, 10 V,+/- 20%, 0.08 ohm, 3216-18 SMD", Cap_Case=3216-18, Manufacturer=Kemet, Tolerance_%=20%, Value1="0.08 ohm", Value2=10V, ValueDisplayed=10µF
C38 C39 C42: library part CMP-0007081-4, "CAP, CERM, 1000 pF, 100 V, +/- 10%, X7R, AEC-Q200 Grade 1, 0603", Alternate Manufacturer="Wurth Elektronik", Alternate PartNumber=885012006085, Cap_Case=0603, Manufacturer=TDK, Supplier Part Number 1=445-5806-1-ND, TempCo=X7R, Tolerance_%=10%, Value1="1.97137 ohm", Value2=100V, ValueDisplayed=1000pF
C40: library part CMP-0091702-1, "4.7µF ±10% 25V Ceramic Capacitor X5R 0603 (1608 Metric)", Digikey Part Number=490-14462-1-ND, Manufacturer=Murata, Mouser Part Number=81-GRM188R61E475KE5D, Operating Temperature Range="-55°C to +85°C", TempCo=15%, Temperature Characteristic=X5R, Tolerance_%=10%, ValueDisplayed=4.7uF
C41: library part CMP-08246-002186-1, "Cap Ceramic 100nF 25V X7R 10% Pad SMD 0603 +125°C Automotive T/R", Capacitance=100nF, Case Code (Imperial)=0603, Case Code (Metric)=1608, Dielectric=X7R, Max Operating Temperature=125°C, Min Operating Temperature=-55°C, Package Quantity=1, Ratings=AEC-Q200, Tolerance=10%, Voltage Rating=25V
C43: library part CMP-08246-007260-1, "CAP CER 10UF 100V X7S 2220", Capacitance=10uF, Case Code (Imperial)=2220, Case Code (Metric)=5750, Dielectric=X7S, Max Operating Temperature=125°C, Min Operating Temperature=-55°C, Package Quantity=1, Resistor Type=Ceramic, Tolerance=20%, Voltage Rating=100V
C47 C48 C49 C50: library part CMP-0064916-2, "CAP, CERM, 10 pF, 50 V,+/- 1%, C0G/NP0, 0402", Alternate Manufacturer="Wurth Elektronik", Alternate PartNumber=885012005055, Cap_Case=0402, Manufacturer=MuRata, Supplier Part Number 1=490-6186-1-ND, TempCo=C0G/NP0, Tolerance_%=1%, Value1=Unknown, Value2=50V, ValueDisplayed=10pF
C51: library part CMP-0007836-2, "CAP, CERM, 2.2 uF, 50 V, +/- 10%, X5R, 0805", Cap_Case=0805, Manufacturer=TDK, Supplier Part Number 1=445-5976-1-ND, TempCo=X5R, Tolerance_%=10%, Value1="0.00366 ohm", Value2=50V, ValueDisplayed=2.2uF
C53: library part CMP-0007078-4, "CAP, CERM, 0.1 uF, 50 V, +/- 10%, X7R, AEC-Q200 Grade 1, 0603", Alternate Manufacturer="Wurth Elektronik", Alternate PartNumber=885012206095, Cap_Case=0603, Manufacturer=TDK, Supplier Part Number 1=445-5666-1-ND, TempCo=X7R, Tolerance_%=10%, Value1="0.0296 ohm", Value2=50V, ValueDisplayed=0.1uF
D1 D3 D7: library part CMP-1426-00009-1, "SMD mono-color Chip LED, WL-SMCW, Bright Green", Color="Bright Green", Manufacturer="Wuerth Elektronik"
D2: library part CMP-1426-00010-1, "SMD mono-color Chip LED, WL-SMCW, Super Red", Color="Super Red", Manufacturer="Wuerth Elektronik"
D4: library part CMP-08607-000009-1, "TVS DIODE 36V 58.1V DO214AC", Breakdown Voltage=40V, Clamping Voltage=58.1V, Manufacturer="Littelfuse Inc", Max Junction Temp=+150°C, Peak Pulse Current=6.9A, Peak Pulse Power=400W, Reverse Standoff Voltage=36V, Temperature="-65°C to +150°C", Temperature Range Low=-65°C
D5: library part CMP-0002947-3, "LED, Red, SMD", Color=Red, Manufacturer="Wurth Elektronik", Power_TotalModule=72mW, Value1=0.072W, Value2=2V
D6: "LED, Green, SMD", Color=green, Manufacturer="Wurth Elektronik", PartNumber=150060VS75000, Value1=W, Value2=2V
F1: library part CMP-0081016-1, "Fuse, 15 A, 250 VAC, 100 VDC, SMD", Irating_A=15A, Manufacturer=Littelfuse
F2: library part CMP-0077200-3, "Fuse, 30 A, 250 VAC, 100 VDC, SMD", Irating_A=30A, Manufacturer=Littelfuse, Supplier Part Number 1=F6439CT-ND
FID1 FID2 FID3: library part CMP-0077181-1, "Fiducial mark.  There is nothing to buy or mount.", Manufacturer=N/A
H1 H2 H3 H4: library part CMP-0003620-1, "Bumpon, Hemisphere, 0.44 X 0.20, Clear", Manufacturer=3M, Supplier Part Number 1=SJ5303-7-ND
J1: library part CMP-77940-000002-1, "CONN HEADER VERT 3POS 2.54MM", Alternative Manufacturer="Wurth Elektronik", Alternative PartNumber=61900311121, Current Rating=3A, Manufacturer="Metz Connect", Temperature="-40°C to +105°C", Temperature Range High=+105°C, Temperature Range Low=-40°C
J2: library part CMP-0075595-1, "Header, 2.54mm, 8x2, Gold, SMT", Alternate Manufacturer="Wurth Elektronik", Alternate PartNumber=61001621121, Color=Black, Current_A=4.9A, Manufacturer=Samtec, Supplier Part Number 1=SAM8884-ND, Voltage_V=475V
